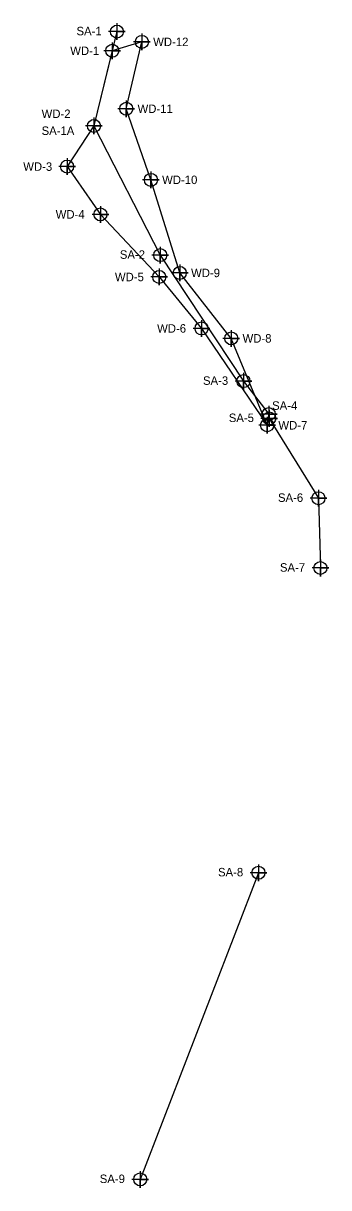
# Model space of a CAD drawing. Extents: x 1487542 to 1488992, y 498290 to 499418.
# Drawn here: x 1487541.5 to 1487651.4, y 498290.2 to 498708.9 of the extents above; entities that cross this region are included whole.
import ezdxf

# ---------------------------------------------------------------- set-up
doc = ezdxf.new("R2010")
doc.units = 0
for name, color, linetype in [('Exist Environmental Wetland Boundary', 7, 'Continuous'), ('Exist Environmental Wetland Boundary Cogo Point CELL', 7, 'Continuous'), ('Exist Environmental Wetland Boundary Text', 7, 'Continuous'), ('Exist Hydro Jurisdictional Stream or Body of Water Mitigable', 7, 'Continuous'), ('Exist Hydro Jurisdictional Stream or Body of Water Mitigable Cogo Point CELL', 7, 'Continuous'), ('Exist Hydro Jurisdictional Stream or Body of Water Mitigable Text', 7, 'Continuous'), ('WEX', 7, 'Continuous')]:
    doc.layers.add(name, color=color, linetype=linetype)

msp = doc.modelspace()

# ---------------------------------------------------------------- linework, layer by layer
at = {"layer": 'Exist Environmental Wetland Boundary'}
msp.add_lwpolyline([(1487629.27, 498564.35), (1487616.38, 498595.61), (1487597.86, 498619.14), (1487587.44, 498652.62), (1487578.6, 498678.18), (1487584.22, 498702.23), (1487573.56, 498699.03), (1487566.96, 498672), (1487557.29, 498657.39), (1487569.27, 498640.21), (1487590.45, 498617.69), (1487605.69, 498599.19)], close=True, dxfattribs=at)
at = {"layer": 'Exist Environmental Wetland Boundary Cogo Point CELL'}
for points in [[(1487584.22, 498705.23), (1487584.22, 498699.23), (1487584.22, 498702.23), (1487587.22, 498702.23), (1487581.22, 498702.23)], [(1487573.56, 498702.03), (1487573.56, 498696.03), (1487573.56, 498699.03), (1487576.56, 498699.03), (1487570.56, 498699.03)], [(1487578.6, 498681.18), (1487578.6, 498675.18), (1487578.6, 498678.18), (1487581.6, 498678.18), (1487575.6, 498678.18)], [(1487566.96, 498675), (1487566.96, 498669), (1487566.96, 498672), (1487569.96, 498672), (1487563.96, 498672)], [(1487557.29, 498660.39), (1487557.29, 498654.39), (1487557.29, 498657.39), (1487560.29, 498657.39), (1487554.29, 498657.39)], [(1487587.44, 498655.62), (1487587.44, 498649.62), (1487587.44, 498652.62), (1487590.44, 498652.62), (1487584.44, 498652.62)], [(1487569.27, 498643.21), (1487569.27, 498637.21), (1487569.27, 498640.21), (1487572.27, 498640.21), (1487566.27, 498640.21)], [(1487590.45, 498620.69), (1487590.45, 498614.69), (1487590.45, 498617.69), (1487593.45, 498617.69), (1487587.45, 498617.69)], [(1487597.86, 498622.14), (1487597.86, 498616.14), (1487597.86, 498619.14), (1487600.86, 498619.14), (1487594.86, 498619.14)], [(1487605.69, 498602.19), (1487605.69, 498596.19), (1487605.69, 498599.19), (1487608.69, 498599.19), (1487602.69, 498599.19)], [(1487616.38, 498598.61), (1487616.38, 498592.61), (1487616.38, 498595.61), (1487619.38, 498595.61), (1487613.38, 498595.61)], [(1487629.27, 498567.35), (1487629.27, 498561.35), (1487629.27, 498564.35), (1487632.27, 498564.35), (1487626.27, 498564.35)]]:
    msp.add_lwpolyline(points, dxfattribs=at)
for centre in [(1487584.22, 498702.23), (1487573.56, 498699.03), (1487578.6, 498678.18), (1487566.96, 498672), (1487557.29, 498657.39), (1487587.44, 498652.62), (1487569.27, 498640.21), (1487590.45, 498617.69), (1487597.86, 498619.14), (1487605.69, 498599.19), (1487616.38, 498595.61), (1487629.27, 498564.35)]:
    msp.add_circle(centre, 2.34, dxfattribs=at)
at = {"layer": 'Exist Hydro Jurisdictional Stream or Body of Water Mitigable'}
for points in [[(1487575.25, 498705.92), (1487566.96, 498672), (1487590.84, 498625.54), (1487620.76, 498580.23), (1487629.85, 498568.35), (1487630.05, 498566.84), (1487647.74, 498538.13), (1487648.45, 498513.03)], [(1487626.17, 498403.45), (1487583.61, 498293.17)]]:
    msp.add_lwpolyline(points, dxfattribs=at)
at = {"layer": 'Exist Hydro Jurisdictional Stream or Body of Water Mitigable Cogo Point CELL'}
for points in [[(1487575.25, 498708.92), (1487575.25, 498702.92), (1487575.25, 498705.92), (1487578.25, 498705.92), (1487572.25, 498705.92)], [(1487590.84, 498628.54), (1487590.84, 498622.54), (1487590.84, 498625.54), (1487593.84, 498625.54), (1487587.84, 498625.54)], [(1487620.76, 498583.23), (1487620.76, 498577.23), (1487620.76, 498580.23), (1487623.76, 498580.23), (1487617.76, 498580.23)], [(1487629.85, 498571.35), (1487629.85, 498565.35), (1487629.85, 498568.35), (1487632.85, 498568.35), (1487626.85, 498568.35)], [(1487630.05, 498569.84), (1487630.05, 498563.84), (1487630.05, 498566.84), (1487633.05, 498566.84), (1487627.05, 498566.84)], [(1487647.74, 498541.13), (1487647.74, 498535.13), (1487647.74, 498538.13), (1487650.74, 498538.13), (1487644.74, 498538.13)], [(1487648.45, 498516.03), (1487648.45, 498510.03), (1487648.45, 498513.03), (1487651.45, 498513.03), (1487645.45, 498513.03)], [(1487626.17, 498406.45), (1487626.17, 498400.45), (1487626.17, 498403.45), (1487629.17, 498403.45), (1487623.17, 498403.45)], [(1487583.61, 498296.17), (1487583.61, 498290.17), (1487583.61, 498293.17), (1487586.61, 498293.17), (1487580.61, 498293.17)]]:
    msp.add_lwpolyline(points, dxfattribs=at)
for centre in [(1487575.25, 498705.92), (1487590.84, 498625.54), (1487620.76, 498580.23), (1487629.85, 498568.35), (1487630.05, 498566.84), (1487647.74, 498538.13), (1487648.45, 498513.03), (1487626.17, 498403.45), (1487583.61, 498293.17)]:
    msp.add_circle(centre, 2.34, dxfattribs=at)
at = {"layer": 'WEX'}
for p, q in [((1487573.56, 498699.03), (1487573.56, 498699.03)), ((1487584.22, 498702.23), (1487584.22, 498702.23)), ((1487578.6, 498678.18), (1487578.6, 498678.18)), ((1487566.96, 498672), (1487566.96, 498672)), ((1487557.29, 498657.39), (1487557.29, 498657.39)), ((1487587.44, 498652.62), (1487587.44, 498652.62)), ((1487569.27, 498640.21), (1487569.27, 498640.21)), ((1487590.84, 498625.54), (1487590.84, 498625.54)), ((1487590.45, 498617.69), (1487590.45, 498617.69)), ((1487597.86, 498619.14), (1487597.86, 498619.14)), ((1487605.69, 498599.19), (1487605.69, 498599.19)), ((1487616.38, 498595.61), (1487616.38, 498595.61)), ((1487620.76, 498580.23), (1487620.76, 498580.23)), ((1487620.76, 498580.23), (1487620.76, 498580.23)), ((1487629.83, 498568.12), (1487629.83, 498568.12)), ((1487629.83, 498568.12), (1487629.83, 498568.12)), ((1487630.05, 498566.84), (1487630.05, 498566.84)), ((1487630.05, 498566.84), (1487630.05, 498566.84)), ((1487629.27, 498564.35), (1487629.27, 498564.35)), ((1487647.74, 498538.13), (1487647.74, 498538.13)), ((1487648.45, 498513.03), (1487648.45, 498513.03)), ((1487626.17, 498403.45), (1487626.17, 498403.45)), ((1487583.61, 498293.17), (1487583.61, 498293.17))]:
    msp.add_line(p, q, dxfattribs=at)

# ---------------------------------------------------------------- texts
at = {"layer": 'Exist Environmental Wetland Boundary Text'}
for s, p in [('WD-12', (1487588.28, 498700.71)), ('WD-1', (1487558.43, 498697.51)), ('WD-2', (1487548.13, 498674.85)), ('WD-11', (1487582.66, 498676.65)), ('SA-1A', (1487548.13, 498668.76)), ('WD-3', (1487541.52, 498655.86)), ('WD-10', (1487591.49, 498651.1)), ('WD-4', (1487553.2, 498638.68)), ('WD-5', (1487574.51, 498616.16)), ('WD-9', (1487601.91, 498617.62)), ('WD-6', (1487589.7, 498597.66)), ('WD-8', (1487620.44, 498594.09)), ('WD-7', (1487633.33, 498562.83))]:
    msp.add_text(s, height=3.047, dxfattribs=at).set_placement(p)
at = {"layer": 'Exist Hydro Jurisdictional Stream or Body of Water Mitigable Text'}
for s, p in [('SA-1', (1487560.69, 498704.6)), ('SA-2', (1487576.28, 498624.22)), ('SA-3', (1487606.2, 498578.9)), ('SA-4', (1487631.08, 498569.92)), ('SA-5', (1487615.49, 498565.52)), ('SA-6', (1487633.18, 498536.81)), ('SA-7', (1487633.88, 498511.71)), ('SA-8', (1487611.61, 498402.13)), ('SA-9', (1487569.05, 498291.85))]:
    msp.add_text(s, height=3.047, dxfattribs=at).set_placement(p)

doc.saveas('drawing.dxf')
